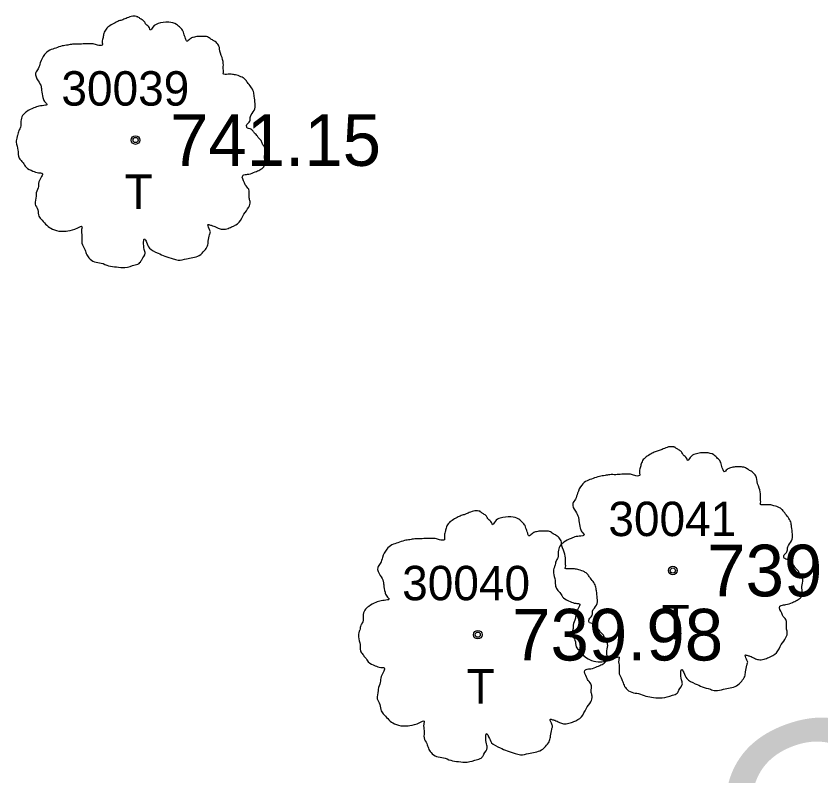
# Model space of a CAD drawing. Extents: x 1375131 to 1378678, y 999028 to 1004053.
# Drawn here: x 1376846.63 to 1376870.03, y 1002770.23 to 1002792.3 of the extents above; entities that cross this region are included whole.
import ezdxf

# ---------------------------------------------------------------- set-up
doc = ezdxf.new("R2010")
doc.units = 0
for name, color, linetype in [('RD_EX_TX_VEG_ELEV', 7, 'Continuous'), ('RD_EX_VEG', 7, 'Continuous'), ('RD_EX_VEG_txCode', 7, 'Continuous'), ('RD_HC_Data', 7, 'Continuous'), ('RD_SMD_Locator', 7, 'Continuous')]:
    doc.layers.add(name, color=color, linetype=linetype)

msp = doc.modelspace()

# ---------------------------------------------------------------- linework, layer by layer
at = {"layer": 'RD_EX_VEG'}
for centre, radius in [((1376850.107, 1002788.704), 0.125), ((1376850.101, 1002788.695), 0.00005), ((1376865.727, 1002776.196), 0.125), ((1376865.721, 1002776.187), 0.00005), ((1376860.055, 1002774.332), 0.125), ((1376860.049, 1002774.323), 0.00005)]:
    msp.add_circle(centre, radius, dxfattribs=at)
for points in [[(1376850.173, 1002792.288), (1376850.023, 1002792.3), (1376849.861, 1002792.25), (1376849.736, 1002792.2), (1376849.623, 1002792.163), (1376849.511, 1002792.113), (1376849.361, 1002792.025), (1376849.248, 1002791.925), (1376849.186, 1002791.8), (1376849.161, 1002791.688), (1376849.136, 1002791.55), (1376849.136, 1002791.463), (1376849.073, 1002791.45), (1376848.998, 1002791.463), (1376848.874, 1002791.5), (1376848.749, 1002791.5), (1376848.624, 1002791.5), (1376848.449, 1002791.488), (1376848.274, 1002791.488), (1376848.136, 1002791.463), (1376847.974, 1002791.438), (1376847.787, 1002791.376), (1376847.612, 1002791.313), (1376847.462, 1002791.188), (1376847.337, 1002790.951), (1376847.274, 1002790.776), (1376847.199, 1002790.651), (1376847.274, 1002790.426), (1376847.362, 1002790.251), (1376847.374, 1002790.151), (1376847.412, 1002789.939), (1376847.462, 1002789.826), (1376847.524, 1002789.726), (1376847.487, 1002789.714), (1376847.299, 1002789.689), (1376847.149, 1002789.639), (1376846.937, 1002789.526), (1376846.824, 1002789.414), (1376846.774, 1002789.251), (1376846.762, 1002789.077), (1376846.712, 1002788.977), (1376846.675, 1002788.839), (1376846.662, 1002788.802), (1376846.637, 1002788.639), (1376846.687, 1002788.414), (1376846.7, 1002788.239), (1376846.762, 1002788.127), (1376846.837, 1002788.04), (1376846.924, 1002787.915), (1376847.124, 1002787.802), (1376847.287, 1002787.752), (1376847.387, 1002787.74), (1376847.299, 1002787.49), (1376847.274, 1002787.315), (1376847.212, 1002787.115), (1376847.212, 1002787.077), (1376847.187, 1002786.84), (1376847.262, 1002786.678), (1376847.299, 1002786.49), (1376847.387, 1002786.378), (1376847.524, 1002786.228), (1376847.687, 1002786.115), (1376847.936, 1002786.053), (1376848.136, 1002786.065), (1376848.424, 1002786.153), (1376848.549, 1002786.19), (1376848.536, 1002786.103), (1376848.549, 1002785.915), (1376848.549, 1002785.703), (1376848.624, 1002785.541), (1376848.674, 1002785.403), (1376848.749, 1002785.278), (1376848.911, 1002785.166), (1376849.111, 1002785.128), (1376849.323, 1002785.053), (1376849.548, 1002785.016), (1376849.798, 1002785.003), (1376850.098, 1002785.078), (1376850.235, 1002785.141), (1376850.285, 1002785.228), (1376850.385, 1002785.416), (1376850.36, 1002785.528), (1376850.373, 1002785.828), (1376850.423, 1002785.74), (1376850.51, 1002785.566), (1376850.76, 1002785.416), (1376850.96, 1002785.328), (1376851.198, 1002785.253), (1376851.347, 1002785.216), (1376851.585, 1002785.253), (1376851.772, 1002785.291), (1376851.96, 1002785.353), (1376852.11, 1002785.491), (1376852.197, 1002785.628), (1376852.222, 1002785.765), (1376852.26, 1002785.953), (1376852.285, 1002786.04)], [(1376852.285, 1002786.04), (1376852.247, 1002786.128), (1376852.222, 1002786.253), (1376852.26, 1002786.24), (1376852.347, 1002786.215), (1376852.484, 1002786.153), (1376852.597, 1002786.115), (1376852.759, 1002786.128), (1376852.897, 1002786.178), (1376853.122, 1002786.315), (1376853.259, 1002786.553), (1376853.397, 1002786.753), (1376853.434, 1002786.915), (1376853.409, 1002787.027), (1376853.397, 1002787.277), (1376853.297, 1002787.402), (1376853.272, 1002787.465), (1376853.222, 1002787.665), (1376853.259, 1002787.69), (1376853.397, 1002787.715), (1376853.584, 1002787.777), (1376853.721, 1002787.84), (1376853.834, 1002787.927), (1376853.871, 1002788.04), (1376853.859, 1002788.239), (1376853.884, 1002788.439), (1376853.846, 1002788.514), (1376853.796, 1002788.589), (1376853.759, 1002788.689), (1376853.684, 1002788.764), (1376853.634, 1002788.839), (1376853.584, 1002788.889), (1376853.522, 1002788.964), (1376853.434, 1002789.027), (1376853.359, 1002789.052), (1376853.334, 1002789.127), (1376853.409, 1002789.226), (1376853.434, 1002789.276), (1376853.447, 1002789.389), (1376853.559, 1002789.564), (1376853.584, 1002789.764), (1376853.559, 1002789.976), (1376853.534, 1002790.114), (1376853.459, 1002790.251), (1376853.359, 1002790.376), (1376853.297, 1002790.463), (1376853.209, 1002790.526), (1376853.047, 1002790.588), (1376852.922, 1002790.613), (1376852.747, 1002790.613), (1376852.647, 1002790.638), (1376852.659, 1002790.663), (1376852.659, 1002790.738), (1376852.659, 1002790.876), (1376852.622, 1002791.101), (1376852.547, 1002791.351), (1376852.547, 1002791.363), (1376852.497, 1002791.488), (1376852.385, 1002791.588), (1376852.297, 1002791.638), (1376852.197, 1002791.7), (1376852.072, 1002791.713), (1376851.922, 1002791.713), (1376851.785, 1002791.688), (1376851.685, 1002791.638), (1376851.597, 1002791.575), (1376851.56, 1002791.65), (1376851.51, 1002791.8), (1376851.485, 1002791.875), (1376851.41, 1002791.963), (1376851.298, 1002792.063), (1376851.073, 1002792.125), (1376850.76, 1002792.088), (1376850.61, 1002791.988), (1376850.535, 1002791.9), (1376850.51, 1002791.963), (1376850.41, 1002792.063), (1376850.36, 1002792.15), (1376850.273, 1002792.213), (1376850.198, 1002792.263), (1376850.148, 1002792.288)], [(1376865.793, 1002779.78), (1376865.643, 1002779.792), (1376865.481, 1002779.742), (1376865.356, 1002779.692), (1376865.243, 1002779.655), (1376865.131, 1002779.605), (1376864.981, 1002779.517), (1376864.868, 1002779.417), (1376864.806, 1002779.292), (1376864.781, 1002779.18), (1376864.756, 1002779.042), (1376864.756, 1002778.955), (1376864.693, 1002778.942), (1376864.618, 1002778.955), (1376864.494, 1002778.992), (1376864.369, 1002778.992), (1376864.244, 1002778.992), (1376864.069, 1002778.98), (1376863.894, 1002778.98), (1376863.756, 1002778.955), (1376863.594, 1002778.93), (1376863.407, 1002778.868), (1376863.232, 1002778.805), (1376863.082, 1002778.68), (1376862.957, 1002778.443), (1376862.894, 1002778.268), (1376862.819, 1002778.143), (1376862.894, 1002777.918), (1376862.982, 1002777.743), (1376862.994, 1002777.643), (1376863.032, 1002777.431), (1376863.082, 1002777.318), (1376863.144, 1002777.218), (1376863.107, 1002777.206), (1376862.919, 1002777.181), (1376862.769, 1002777.131), (1376862.557, 1002777.018), (1376862.444, 1002776.906), (1376862.394, 1002776.743), (1376862.382, 1002776.569), (1376862.332, 1002776.469), (1376862.295, 1002776.331), (1376862.282, 1002776.294), (1376862.257, 1002776.131), (1376862.307, 1002775.906), (1376862.32, 1002775.731), (1376862.382, 1002775.619), (1376862.457, 1002775.532), (1376862.544, 1002775.407), (1376862.744, 1002775.294), (1376862.907, 1002775.244), (1376863.007, 1002775.232), (1376862.919, 1002774.982), (1376862.894, 1002774.807), (1376862.832, 1002774.607), (1376862.832, 1002774.569), (1376862.807, 1002774.332), (1376862.882, 1002774.17), (1376862.919, 1002773.982), (1376863.007, 1002773.87), (1376863.144, 1002773.72), (1376863.307, 1002773.607), (1376863.556, 1002773.545), (1376863.756, 1002773.557), (1376864.044, 1002773.645), (1376864.169, 1002773.682), (1376864.156, 1002773.595), (1376864.169, 1002773.407), (1376864.169, 1002773.195), (1376864.244, 1002773.033), (1376864.294, 1002772.895), (1376864.369, 1002772.77), (1376864.531, 1002772.658), (1376864.731, 1002772.62), (1376864.943, 1002772.545), (1376865.168, 1002772.508), (1376865.418, 1002772.495), (1376865.718, 1002772.57), (1376865.855, 1002772.633), (1376865.905, 1002772.72), (1376866.005, 1002772.908), (1376865.98, 1002773.02), (1376865.993, 1002773.32), (1376866.043, 1002773.232), (1376866.13, 1002773.058), (1376866.38, 1002772.908), (1376866.58, 1002772.82), (1376866.818, 1002772.745), (1376866.967, 1002772.708), (1376867.205, 1002772.745), (1376867.392, 1002772.783), (1376867.58, 1002772.845), (1376867.73, 1002772.983), (1376867.817, 1002773.12), (1376867.842, 1002773.257), (1376867.88, 1002773.445), (1376867.905, 1002773.532)], [(1376867.905, 1002773.532), (1376867.867, 1002773.62), (1376867.842, 1002773.745), (1376867.88, 1002773.732), (1376867.967, 1002773.707), (1376868.104, 1002773.645), (1376868.217, 1002773.607), (1376868.379, 1002773.62), (1376868.517, 1002773.67), (1376868.742, 1002773.807), (1376868.879, 1002774.045), (1376869.017, 1002774.245), (1376869.054, 1002774.407), (1376869.029, 1002774.519), (1376869.017, 1002774.769), (1376868.917, 1002774.894), (1376868.892, 1002774.957), (1376868.842, 1002775.157), (1376868.879, 1002775.182), (1376869.017, 1002775.207), (1376869.204, 1002775.269), (1376869.341, 1002775.332), (1376869.454, 1002775.419), (1376869.491, 1002775.532), (1376869.479, 1002775.731), (1376869.504, 1002775.931), (1376869.466, 1002776.006), (1376869.416, 1002776.081), (1376869.379, 1002776.181), (1376869.304, 1002776.256), (1376869.254, 1002776.331), (1376869.204, 1002776.381), (1376869.142, 1002776.456), (1376869.054, 1002776.519), (1376868.979, 1002776.544), (1376868.954, 1002776.619), (1376869.029, 1002776.718), (1376869.054, 1002776.768), (1376869.067, 1002776.881), (1376869.179, 1002777.056), (1376869.204, 1002777.256), (1376869.179, 1002777.468), (1376869.154, 1002777.606), (1376869.079, 1002777.743), (1376868.979, 1002777.868), (1376868.917, 1002777.955), (1376868.829, 1002778.018), (1376868.667, 1002778.08), (1376868.542, 1002778.105), (1376868.367, 1002778.105), (1376868.267, 1002778.13), (1376868.279, 1002778.155), (1376868.279, 1002778.23), (1376868.279, 1002778.368), (1376868.242, 1002778.593), (1376868.167, 1002778.843), (1376868.167, 1002778.855), (1376868.117, 1002778.98), (1376868.005, 1002779.08), (1376867.917, 1002779.13), (1376867.817, 1002779.192), (1376867.692, 1002779.205), (1376867.542, 1002779.205), (1376867.405, 1002779.18), (1376867.305, 1002779.13), (1376867.217, 1002779.067), (1376867.18, 1002779.142), (1376867.13, 1002779.292), (1376867.105, 1002779.367), (1376867.03, 1002779.455), (1376866.918, 1002779.555), (1376866.693, 1002779.617), (1376866.38, 1002779.58), (1376866.23, 1002779.48), (1376866.155, 1002779.392), (1376866.13, 1002779.455), (1376866.03, 1002779.555), (1376865.98, 1002779.642), (1376865.893, 1002779.705), (1376865.818, 1002779.755), (1376865.768, 1002779.78)], [(1376860.121, 1002777.916), (1376859.971, 1002777.928), (1376859.809, 1002777.878), (1376859.684, 1002777.828), (1376859.571, 1002777.791), (1376859.459, 1002777.741), (1376859.309, 1002777.653), (1376859.196, 1002777.553), (1376859.134, 1002777.428), (1376859.109, 1002777.316), (1376859.084, 1002777.178), (1376859.084, 1002777.091), (1376859.021, 1002777.078), (1376858.946, 1002777.091), (1376858.822, 1002777.128), (1376858.697, 1002777.128), (1376858.572, 1002777.128), (1376858.397, 1002777.116), (1376858.222, 1002777.116), (1376858.084, 1002777.091), (1376857.922, 1002777.066), (1376857.735, 1002777.004), (1376857.56, 1002776.941), (1376857.41, 1002776.816), (1376857.285, 1002776.579), (1376857.222, 1002776.404), (1376857.147, 1002776.279), (1376857.222, 1002776.054), (1376857.31, 1002775.879), (1376857.322, 1002775.779), (1376857.36, 1002775.567), (1376857.41, 1002775.454), (1376857.472, 1002775.354), (1376857.435, 1002775.342), (1376857.247, 1002775.317), (1376857.097, 1002775.267), (1376856.885, 1002775.154), (1376856.772, 1002775.042), (1376856.722, 1002774.879), (1376856.71, 1002774.705), (1376856.66, 1002774.605), (1376856.623, 1002774.467), (1376856.61, 1002774.43), (1376856.585, 1002774.267), (1376856.635, 1002774.042), (1376856.648, 1002773.867), (1376856.71, 1002773.755), (1376856.785, 1002773.668), (1376856.872, 1002773.543), (1376857.072, 1002773.43), (1376857.235, 1002773.38), (1376857.335, 1002773.368), (1376857.247, 1002773.118), (1376857.222, 1002772.943), (1376857.16, 1002772.743), (1376857.16, 1002772.705), (1376857.135, 1002772.468), (1376857.21, 1002772.306), (1376857.247, 1002772.118), (1376857.335, 1002772.006), (1376857.472, 1002771.856), (1376857.635, 1002771.743), (1376857.884, 1002771.681), (1376858.084, 1002771.693), (1376858.372, 1002771.781), (1376858.497, 1002771.818), (1376858.484, 1002771.731), (1376858.497, 1002771.543), (1376858.497, 1002771.331), (1376858.572, 1002771.169), (1376858.622, 1002771.031), (1376858.697, 1002770.906), (1376858.859, 1002770.794), (1376859.059, 1002770.756), (1376859.271, 1002770.681), (1376859.496, 1002770.644), (1376859.746, 1002770.631), (1376860.046, 1002770.706), (1376860.183, 1002770.769), (1376860.233, 1002770.856), (1376860.333, 1002771.044), (1376860.308, 1002771.156), (1376860.321, 1002771.456), (1376860.371, 1002771.368), (1376860.458, 1002771.194), (1376860.708, 1002771.044), (1376860.908, 1002770.956), (1376861.146, 1002770.881), (1376861.295, 1002770.844), (1376861.533, 1002770.881), (1376861.72, 1002770.919), (1376861.908, 1002770.981), (1376862.058, 1002771.119), (1376862.145, 1002771.256), (1376862.17, 1002771.393), (1376862.208, 1002771.581), (1376862.233, 1002771.668)], [(1376862.233, 1002771.668), (1376862.195, 1002771.756), (1376862.17, 1002771.881), (1376862.208, 1002771.868), (1376862.295, 1002771.843), (1376862.432, 1002771.781), (1376862.545, 1002771.743), (1376862.707, 1002771.756), (1376862.845, 1002771.806), (1376863.07, 1002771.943), (1376863.207, 1002772.181), (1376863.345, 1002772.381), (1376863.382, 1002772.543), (1376863.357, 1002772.655), (1376863.345, 1002772.905), (1376863.245, 1002773.03), (1376863.22, 1002773.093), (1376863.17, 1002773.293), (1376863.207, 1002773.318), (1376863.345, 1002773.343), (1376863.532, 1002773.405), (1376863.669, 1002773.468), (1376863.782, 1002773.555), (1376863.819, 1002773.668), (1376863.807, 1002773.867), (1376863.832, 1002774.067), (1376863.794, 1002774.142), (1376863.744, 1002774.217), (1376863.707, 1002774.317), (1376863.632, 1002774.392), (1376863.582, 1002774.467), (1376863.532, 1002774.517), (1376863.47, 1002774.592), (1376863.382, 1002774.655), (1376863.307, 1002774.68), (1376863.282, 1002774.755), (1376863.357, 1002774.854), (1376863.382, 1002774.904), (1376863.395, 1002775.017), (1376863.507, 1002775.192), (1376863.532, 1002775.392), (1376863.507, 1002775.604), (1376863.482, 1002775.742), (1376863.407, 1002775.879), (1376863.307, 1002776.004), (1376863.245, 1002776.091), (1376863.157, 1002776.154), (1376862.995, 1002776.216), (1376862.87, 1002776.241), (1376862.695, 1002776.241), (1376862.595, 1002776.266), (1376862.607, 1002776.291), (1376862.607, 1002776.366), (1376862.607, 1002776.504), (1376862.57, 1002776.729), (1376862.495, 1002776.979), (1376862.495, 1002776.991), (1376862.445, 1002777.116), (1376862.333, 1002777.216), (1376862.245, 1002777.266), (1376862.145, 1002777.328), (1376862.02, 1002777.341), (1376861.87, 1002777.341), (1376861.733, 1002777.316), (1376861.633, 1002777.266), (1376861.545, 1002777.203), (1376861.508, 1002777.278), (1376861.458, 1002777.428), (1376861.433, 1002777.503), (1376861.358, 1002777.591), (1376861.246, 1002777.691), (1376861.021, 1002777.753), (1376860.708, 1002777.716), (1376860.558, 1002777.616), (1376860.483, 1002777.528), (1376860.458, 1002777.591), (1376860.358, 1002777.691), (1376860.308, 1002777.778), (1376860.221, 1002777.841), (1376860.146, 1002777.891), (1376860.096, 1002777.916)]]:
    msp.add_spline(points, degree=3, dxfattribs=at)
at = {"layer": 'RD_SMD_Locator'}
for centre in [(1376850.107, 1002788.704), (1376865.727, 1002776.196), (1376860.055, 1002774.332)]:
    msp.add_circle(centre, 0.075, dxfattribs=at)

# ---------------------------------------------------------------- texts
at = {"layer": 'RD_EX_TX_VEG_ELEV'}
for s, p in [('741.15', (1376851.107, 1002787.954)), ('739.76', (1376866.727, 1002775.446)), ('739.98', (1376861.055, 1002773.582))]:
    msp.add_text(s, height=1.5, dxfattribs=at).set_placement(p)
at = {"layer": 'RD_EX_VEG_txCode'}
for s, p in [('30039', (1376847.95, 1002789.704)), ('T', (1376849.784, 1002786.704)), ('30041', (1376863.853, 1002777.196)), ('30040', (1376857.858, 1002775.332)), ('T', (1376865.404, 1002774.196)), ('T', (1376859.732, 1002772.332))]:
    msp.add_text(s, height=1, dxfattribs=at).set_placement(p)
at = {"layer": 'RD_HC_Data'}
msp.add_text('PC=34+16.40', height=6, rotation=20.27, dxfattribs=at).set_placement((1376863.181, 1002763.078))

doc.saveas('drawing.dxf')
